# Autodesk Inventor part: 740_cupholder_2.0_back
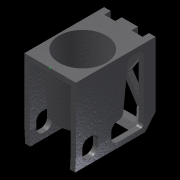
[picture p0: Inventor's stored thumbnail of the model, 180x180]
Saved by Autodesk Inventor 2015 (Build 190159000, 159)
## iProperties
Created: 2016-11
Part Number: 740_cupholder_2.0_back
Material: ABS Plastic
Document SubType Name: Modeling
Designer: Mikael
Density: 1.06 g/cm^3
Appearance: Textured - Gray
Mass: 944.042 g
Surface Area: 2215.58 cm^2
Volume: 890.605 cm^3
Author: Mikael
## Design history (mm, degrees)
sketch "Sketch1"
  geometry: L1 (0, -122.5)-(120, -122.5); L2 (120, -122.5)-(120, 122.5); L3 (120, 122.5)-(0, 67.5); L4 (0, -122.5)-(0, 67.5); 1 further point
  constraints: 8 end point, 2 vertical, 1 perpendicular, 1 point on line
  dimensions: "d0" = 190 distance of L3.end L1.start; "d1" = 120 distance of L1.start L1.end; "d2" = 245 distance of L1.end L2.end; "d13" = 122.5 distance from line of point (0, 0) L1 (= 0.5 x d2)
extrude "Extrusion1" new body sketch "Sketch1" stored distance "d3" = 79; taper "d4" = 0 deg
sketch "Sketch2"
  geometry: L1 (79, 0)-(0, 0) reference; L2 (28.5, 0)-(50.5, 0); L3 (50.5, 0)-(50.5, 25); L4 (50.5, 25)-(28.5, 25); L5 (28.5, 25)-(28.5, 0); L6 (39.5, 294)-(39.5, -49) reference; 1 further point
  constraints: 8 end point, 2 parallel, 1 horizontal, 1 perpendicular, 1 point on line
  dimensions: "d5" = 22 distance between parallel lines of L3 L5; "d6" = 25 distance of L4.end L2.start; "d7" = 11 distance between parallel lines of L6 L5 (= 0.5 x d5)
extrude "Extrusion2" cut sketch "Sketch2" stored distance "d8" = 75; taper "d9" = 0 deg
sketch "Sketch3"
  geometry: L1 (283.012, 50)-(45, 50); L2 (45, 50)-(45, 19); L3 (45, 19)-(200, 8); L4 (200, 8)-(200, 50); L5 (-58.901, 0)-(353.406, 0) reference; L6 (0, -122.5)-(0, 67.5) reference; L7 (45, -50)-(45, -81); L8 (45, -81)-(200, -92); L9 (200, -92)-(200, -50); L10 (294.505, -50)-(45, -50); L11 (120, 83.999)-(120, -122.5) reference; 2 further points
  constraints: 16 end point, 4 vertical, 2 horizontal, 2 point on line
  dimensions: "d10" = 62 diameter of L2.end L1; "d11" = 84 diameter of L3.end L1; "d14" = 50 distance from line of L5 L1.end; "d16" = 155 distance between parallel lines of L4 L2; "d18" = 45 distance between parallel lines of L6 L2 (derived); "d19" = 62 diameter of L7.end L10; "d20" = 84 diameter of L8.end L10; "d21" = 155 distance between parallel lines of L9 L7; "d22" = 45 distance between parallel lines of L6 L7 (= d18); "d23" = 50 distance from line of L5 L7.start (derived); "d61" = 75 distance between parallel lines of L2 L11; "d62" = 100 distance of L7.start L1.end
sketch "Sketch5"
  geometry: 1 further point
node "plan urtag fram"
sketch "Sketch6"
  geometry: L1 (-39.5, 0)-(-11, 0) reference; L2 (-39.5, -222.721)-(-39.5, 0) reference; L3 (39.5, 0)-(-39.5, 0) reference; L4 (-35, 0)-(-39.5, -35); L5 (-39.5, 0)-(-35, 0); L6 (-39.5, 0)-(-39.5, -35); L7 (39.5, 0)-(39.5, -222.721) reference; L8 (11, 0)-(39.5, 0) reference; L9 (35, 0)-(39.5, -35); L10 (39.5, -35)-(39.5, 0); L11 (35, 0)-(39.5, 0); 1 further point
  constraints: 12 end point, 4 collinear, 4 point on line
  dimensions: "d30" = 70 distance of L9.start L4.start; "d31" = 35 horizontal distance of L9.start point (0, -61.362) (derived); "d32" = 35 distance of L9.end L3.start; "d33" = 35 distance of L1.start L4.end (derived)
extrude "Extrusion4" cut sketch "Sketch6" stored distance "d34" = 10; taper "d35" = 0 deg
node "plan urtab gångjärn"
sketch "Sketch7"
  geometry: L1 (79, 0)-(79, -206.499) reference; L2 (79, 0)-(0, 0) reference; L3 (0, -206.499)-(0, 0) reference; L4 (69, -10)-(52, -10); L5 (52, -10)-(52, 0); L6 (52, 0)-(69, 0); L7 (69, 0)-(69, -10); L8 (27, -10)-(10, -10); L9 (10, -10)-(10, 0); L10 (10, 0)-(27, 0); L11 (27, 0)-(27, -10); 1 further point
  constraints: 16 end point, 4 parallel, 2 horizontal, 2 perpendicular, 2 point on line
  dimensions: "d38" = 17 distance of L5.end L6.end; "d40" = 17 distance of L8.start L8.end (derived); "d41" = 10 distance of L6.end L4.start; "d42" = 10 distance of L8.end L9.end (derived); "d45" = 25 distance between parallel lines of L11 L5; "d46" = 12.5 distance from line of point (39.5, -122.5) L5 (derived); "d47" = 10 distance between parallel lines of L1 L7 (derived)
extrude "Extrusion5" cut sketch "Sketch7" distance "d43" = 10; taper "d44" = 0 deg
chamfer "Chamfer1" distance "d49" = 20; stored, may be unused: second distance "d50" = 15, angle "d51" = 20 deg
chamfer "Chamfer2" distance "d52" = 20; stored, may be unused: second distance "d53" = 1, angle "d54" = 20 deg
chamfer "Chamfer3" distance "d55" = 20; stored, may be unused: second distance "d56" = 1, angle "d57" = 20 deg
chamfer "Chamfer4" distance "d58" = 25; stored, may be unused: second distance "d59" = 4, angle "d60" = 20 deg
revolve "Revolution1" stored, may be unused: angle "d15" = 90 deg
revolve "Revolution2" stored, may be unused: angle "d24" = 90 deg
shell "Shell3" dims "d26" = 8
fillet "Fillet3" dims "d70" = 10
sketch "Sketch17"
  geometry: L1 (-24, 0)-(144, 0) reference; 1 further point
split "Split4" sketch "Sketch17"
sketch "Sketch19"
  geometry: L1 (-19, -18)-(-19, -102); L2 (-19, -102)-(8.5, -60); L3 (8.5, -60)-(-19, -18); L4 (-9.438, -18)-(34.438, -18); L5 (34.438, -18)-(12.5, -51.505); L6 (12.5, -51.505)-(-9.438, -18); L7 (12.5, -144)-(12.5, 24) reference; L8 (-52.737, -60)-(71.212, -60); L9 (-17, 0)-(0, 0) reference; L10 (-27, 0)-(-27, -100) reference; L11 (52, -100)-(52, 0) reference; L12 (16.5, -60)-(44, -18); L13 (44, -18)-(44, -102); L14 (44, -102)-(16.5, -60); L15 (-15.985, -112)-(40.985, -112); L16 (12.5, -68.495)-(-15.985, -112); L17 (40.985, -112)-(12.5, -68.495); L18 (8, -18)-(-19, -18) reference; L19 (-26, -120)-(51, -120) reference; 1 further point
  constraints: 26 end point, 4 parallel, 4 symmetric about line, 3 point on line, 1 collinear, 1 horizontal, 1 vertical
  dimensions: "d85" = 60 distance between parallel lines of L9 L8; "d87" = 8 distance between parallel lines of L10 L1; "d88" = 4 distance from line of L2.end L7; "d92" = 8 distance between parallel lines of L3 L6; "d121" = 8 distance between parallel lines of L19 L15; "d122" = 8 distance between parallel lines of L2 L16; "d123" = 8 distance between parallel lines of L14 L17 (derived)
extrude "Extrusion10" cut sketch "Sketch19" distance "d82" = 20; taper "d83" = 0 deg
fillet "Fillet4" dims "d98" = 2
sketch "Sketch22"
  geometry: L1 (99.5, 20)-(75.749, 20); L2 (104.5, 102)-(104.5, 112) reference; L3 (104.5, 112)-(80.397, 112) reference; L4 (104.5, 102)-(104.5, 25); L5 (79.903, 107.553)-(70.779, 25.553); L6 (122.5, 20)-(0, 20) reference; L7 (84.872, 112)-(99.5, 112); L8 (104.5, 102)-(104.5, 107); A1 r 5 centre (84.872, 107) between (84.872, 112) and (79.903, 107.553); A2 r 5 centre (99.5, 107) between (104.5, 107) and (99.5, 112); A3 r 5 centre (99.5, 25) between (99.5, 20) and (104.5, 25); A4 r 5 centre (75.749, 25) between (70.779, 25.553) and (75.749, 20); 4 further points
  constraints: 10 end point, 9 point on line, 8 point on circle, 8 tangent, 4 centre point, 3 collinear, 3 equal radius, 1 horizontal, 1 vertical
  dimensions: "d110" = 5 radius of A1
extrude "Extrusion13" cut sketch "Sketch22" distance "d108" = 8; taper "d109" = 0 deg
mirror "Mirror4"
sketch "Sketch24"
  geometry: L1 (10, 37)-(104.5, 37); L2 (104.5, 37)-(104.5, 13); L3 (99.5, 8)-(10, 8); L4 (10, 8)-(10, 37); L5 (104.5, 107)-(104.5, 25) reference; L6 (27.947, 37)-(72.053, 37) reference; L7 (0, 0)-(107.5, 0) reference; L8 (34.5, 37)-(54.5, 37); L9 (54.5, 37)-(54.5, 8); L10 (54.5, 8)-(34.5, 8); L11 (34.5, 8)-(34.5, 37); L12 (0, 120)-(0, 20) reference; A1 r 5 centre (99.5, 13) between (99.5, 8) and (104.5, 13)
  constraints: 16 end point, 4 parallel, 2 collinear, 2 horizontal, 2 perpendicular, 2 point on circle, 2 point on line, 2 tangent, 1 centre point
  dimensions: "d124" = 5 radius of A1; "d125" = 8 distance between parallel lines of L3 L7; "d128" = 20 distance between parallel lines of L11 L9; "d129" = 50 distance between parallel lines of L2 L9; "d133" = 10 distance between parallel lines of L12 L4
extrude "Extrusion14" cut sketch "Sketch24" distance "d126" = 10; taper "d127" = 0 deg
fillet "Fillet5" dims "d130" = 10
mirror "Mirror6"
fillet "Fillet7" dims "d132" = 8
body "Solid1"
other parameters: "d29" = 90 deg, "d36" = 0
